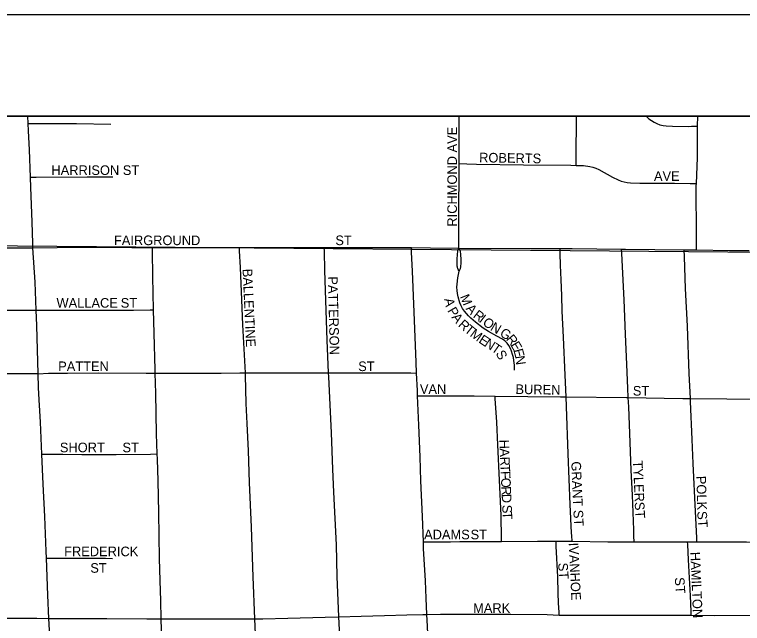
# Model space of a CAD drawing. Extents: x -9.1 to 34, y -3.1 to 22.
# Drawn here: x 5.381 to 6.099, y 20.4 to 21 of the extents above; entities that cross this region are included whole.
import ezdxf

# ---------------------------------------------------------------- set-up
doc = ezdxf.new("R2010")
doc.units = 0
for name, color, linetype in [('GM_X_City_Street', 7, 'Continuous'), ('GM_X_City_Street_Text', 7, 'Continuous'), ('GM_X_Corporation', 7, 'Continuous'), ('GM_X_Section', 7, 'Continuous'), ('GM_X_State_Route', 7, 'Continuous'), ('SH_Data', 7, 'Continuous')]:
    doc.layers.add(name, color=color, linetype=linetype)

msp = doc.modelspace()

# ---------------------------------------------------------------- linework, layer by layer
at = {"layer": 'GM_X_City_Street'}
for points in [[(5.3947, 20.89271), (5.39437, 20.9)], [(5.81948, 20.85303), (5.81945, 20.86152), (5.81951, 20.8769), (5.81946, 20.89235), (5.81958, 20.9)], [(5.93485, 20.85131), (5.93494, 20.86038), (5.93506, 20.87279), (5.93534, 20.88519), (5.93543, 20.89762), (5.93544, 20.9)], [(6.00374, 20.9), (6.00434, 20.89936), (6.00666, 20.89728), (6.00915, 20.89541), (6.01182, 20.8938), (6.01464, 20.89248), (6.01758, 20.89145), (6.0206, 20.89069), (6.02368, 20.89026), (6.0299, 20.88991), (6.04547, 20.88979), (6.04858, 20.88986), (6.05473, 20.88999)], [(6.05473, 20.88999), (6.05481, 20.9)], [(5.3947, 20.89271), (5.39889, 20.89269), (5.41123, 20.89261), (5.44208, 20.89272), (5.47601, 20.89207)], [(5.39691, 20.83962), (5.39575, 20.86667), (5.39504, 20.88525), (5.3947, 20.89271)], [(6.05349, 20.83337), (6.05452, 20.85892), (6.05473, 20.88999)], [(5.81931, 20.76967), (5.81932, 20.77473), (5.81941, 20.80646), (5.81952, 20.84428), (5.81948, 20.85303)], [(5.81948, 20.85303), (5.82724, 20.85281), (5.83656, 20.85254), (5.88318, 20.85185), (5.92982, 20.85146), (5.93485, 20.85131)], [(5.93485, 20.85131), (5.94225, 20.85109), (5.94843, 20.85036), (5.95145, 20.84965), (5.95437, 20.8486), (5.9572, 20.84731), (5.97078, 20.83974), (5.97636, 20.837), (5.97927, 20.83591), (5.98226, 20.83509), (5.98531, 20.83457), (5.98841, 20.83424), (5.99773, 20.83376), (6.0164, 20.83375), (6.03192, 20.8337), (6.04745, 20.83346), (6.05349, 20.83337)], [(5.39691, 20.83962), (5.40229, 20.83964), (5.45279, 20.83987), (5.47175, 20.83996), (5.47807, 20.83994)], [(5.39918, 20.77018), (5.39908, 20.77442), (5.39841, 20.79563), (5.39735, 20.82944), (5.39691, 20.83962)], [(6.0535, 20.768), (6.0535, 20.7734), (6.0535, 20.79361), (6.05332, 20.81863), (6.0534, 20.83103), (6.05349, 20.83337)], [(5.31853, 20.77025), (5.34775, 20.76989), (5.39737, 20.77016), (5.39918, 20.77018)], [(5.39918, 20.77018), (5.44701, 20.77059), (5.49665, 20.77048), (5.51709, 20.77037)], [(5.40252, 20.7086), (5.40215, 20.71792), (5.40135, 20.73619), (5.39918, 20.77018)], [(5.51709, 20.77037), (5.53386, 20.77028), (5.58659, 20.77038), (5.60286, 20.77033)], [(5.51828, 20.70896), (5.51745, 20.74181), (5.51714, 20.76683), (5.51709, 20.77037)], [(5.60888, 20.64679), (5.60726, 20.67648), (5.60632, 20.69398), (5.60541, 20.71888), (5.60381, 20.75055), (5.60302, 20.76712), (5.60286, 20.77033)], [(5.60286, 20.77033), (5.62383, 20.77033), (5.68277, 20.77032), (5.68658, 20.77033)], [(5.68658, 20.77033), (5.72, 20.7704), (5.77247, 20.77022)], [(5.69076, 20.64686), (5.68947, 20.679), (5.68721, 20.7478), (5.68668, 20.76687), (5.68658, 20.77033)], [(5.77247, 20.77022), (5.79137, 20.77015), (5.81931, 20.76967)], [(5.77757, 20.64658), (5.77704, 20.65738), (5.77604, 20.68211), (5.77505, 20.70671), (5.77353, 20.74705), (5.77267, 20.76591), (5.77247, 20.77022)], [(5.81973, 20.74696), (5.81926, 20.74772), (5.81869, 20.74874), (5.8183, 20.74958), (5.81805, 20.7504), (5.81788, 20.75114), (5.81777, 20.75199), (5.81763, 20.75305), (5.81756, 20.75404), (5.81753, 20.75527), (5.81769, 20.75893), (5.81789, 20.76352), (5.81825, 20.7666), (5.81864, 20.76827), (5.81931, 20.76967)], [(5.81973, 20.74696), (5.82035, 20.74838), (5.82081, 20.74966), (5.82117, 20.75118), (5.8213, 20.75253), (5.82141, 20.75383), (5.82148, 20.75527), (5.82159, 20.7583), (5.82121, 20.76364), (5.82076, 20.76635), (5.82018, 20.76808), (5.81931, 20.76967)], [(5.81931, 20.76967), (5.89064, 20.76929), (5.91913, 20.76927)], [(5.92505, 20.623), (5.92412, 20.64455), (5.92236, 20.68182), (5.92123, 20.70755), (5.92078, 20.72298), (5.92018, 20.73839), (5.91958, 20.75288), (5.91926, 20.76462), (5.91913, 20.76927)], [(5.91913, 20.76927), (5.93097, 20.76927), (5.9797, 20.76876)], [(5.98622, 20.62244), (5.98589, 20.63181), (5.985, 20.65488), (5.98369, 20.68505), (5.98217, 20.71885), (5.97992, 20.76448), (5.9797, 20.76876)], [(5.9797, 20.76876), (5.98371, 20.76873), (6.04161, 20.7682)], [(6.04764, 20.62159), (6.04641, 20.64632), (6.04462, 20.69288), (6.04285, 20.73011), (6.04184, 20.76116), (6.04161, 20.7682)], [(6.04161, 20.7682), (6.04267, 20.76819), (6.0535, 20.768)], [(6.0535, 20.768), (6.08609, 20.76743), (6.09513, 20.76738), (6.10549, 20.7674)], [(5.87414, 20.64933), (5.87414, 20.65212), (5.87405, 20.65438), (5.87357, 20.65893), (5.87303, 20.66201), (5.87228, 20.66504), (5.87134, 20.66802), (5.87017, 20.67091), (5.86871, 20.67366), (5.86691, 20.6762), (5.86469, 20.67837), (5.86215, 20.68015), (5.85671, 20.68306), (5.84849, 20.68754), (5.84327, 20.69099), (5.83582, 20.69669), (5.8311, 20.70078), (5.82884, 20.70294), (5.82673, 20.70523), (5.82476, 20.70765), (5.82294, 20.7102), (5.82145, 20.71293), (5.82031, 20.71584), (5.81854, 20.72183), (5.81788, 20.72489), (5.81749, 20.72798), (5.8174, 20.73111), (5.81753, 20.73423), (5.8183, 20.74044), (5.81973, 20.74696)], [(5.32126, 20.70844), (5.33072, 20.70845), (5.38395, 20.70852), (5.40252, 20.7086)], [(5.40252, 20.7086), (5.43023, 20.7087), (5.45591, 20.70871), (5.48041, 20.70871), (5.49827, 20.70872), (5.51494, 20.70889), (5.51828, 20.70896)], [(5.40449, 20.64596), (5.4032, 20.69363), (5.40252, 20.7086)], [(5.51992, 20.64652), (5.5198, 20.64988), (5.51886, 20.68597), (5.51828, 20.70896)], [(5.40449, 20.64596), (5.41473, 20.64637), (5.42067, 20.6465), (5.42715, 20.64663), (5.43336, 20.64665), (5.46433, 20.64671), (5.51076, 20.6465), (5.51992, 20.64652)], [(5.51992, 20.64652), (5.55717, 20.6466), (5.56946, 20.64665), (5.58483, 20.6466), (5.60335, 20.64679), (5.60888, 20.64679)], [(5.52185, 20.5669), (5.52126, 20.58674), (5.52046, 20.62686), (5.51992, 20.64652)], [(5.60888, 20.64679), (5.63737, 20.64683), (5.68391, 20.64691), (5.69076, 20.64686)], [(5.61799, 20.40438), (5.61651, 20.44562), (5.61479, 20.49456), (5.61295, 20.53886), (5.61178, 20.56995), (5.61042, 20.5969), (5.60963, 20.61663), (5.60896, 20.64465), (5.60888, 20.64679)], [(5.69076, 20.64686), (5.72274, 20.64682), (5.74862, 20.6469), (5.76103, 20.64683), (5.77203, 20.64667), (5.77757, 20.64658)], [(5.70101, 20.40644), (5.69939, 20.44603), (5.69846, 20.47721), (5.69608, 20.52917), (5.69502, 20.55179), (5.69357, 20.58771), (5.69092, 20.64282), (5.69076, 20.64686)], [(5.77864, 20.62419), (5.77843, 20.62937), (5.77757, 20.64658)], [(5.77864, 20.62419), (5.7837, 20.62416), (5.80782, 20.62405), (5.83446, 20.62402), (5.85506, 20.62378)], [(5.78429, 20.4803), (5.78326, 20.50505), (5.78191, 20.54032), (5.781, 20.56412), (5.77981, 20.59529), (5.77864, 20.62419)], [(5.86141, 20.48064), (5.86137, 20.48354), (5.86103, 20.5062), (5.8576, 20.5758), (5.8568, 20.59832), (5.85522, 20.62143), (5.85506, 20.62378)], [(5.85506, 20.62378), (5.91941, 20.62305), (5.92505, 20.623)], [(5.93089, 20.48076), (5.93055, 20.48612), (5.93034, 20.48922), (5.92905, 20.51716), (5.92714, 20.56688), (5.92545, 20.6135), (5.92505, 20.623)], [(5.92505, 20.623), (5.98453, 20.62247), (5.98622, 20.62244)], [(5.99218, 20.48012), (5.99199, 20.48572), (5.99177, 20.49194), (5.99042, 20.52614), (5.98917, 20.55099), (5.98812, 20.57808), (5.98681, 20.6133), (5.98622, 20.62244)], [(5.98622, 20.62244), (6.02163, 20.62189), (6.04009, 20.62167), (6.04764, 20.62159)], [(6.05402, 20.48031), (6.05386, 20.484), (6.05271, 20.51025), (6.05041, 20.55738), (6.04932, 20.58118), (6.0478, 20.6184), (6.04764, 20.62159)], [(6.04764, 20.62159), (6.0834, 20.62115), (6.10948, 20.62098)], [(5.40808, 20.56667), (5.41656, 20.56663), (5.42891, 20.56656), (5.44744, 20.56625), (5.48132, 20.56643), (5.51516, 20.5668), (5.52185, 20.5669)], [(5.52574, 20.40439), (5.52525, 20.42218), (5.52474, 20.44217), (5.52418, 20.46388), (5.52373, 20.48623), (5.52327, 20.509), (5.52263, 20.54025), (5.522, 20.56161), (5.52185, 20.5669)], [(5.78429, 20.4803), (5.79231, 20.48032), (5.81098, 20.4803), (5.82025, 20.48049), (5.83269, 20.4806), (5.85043, 20.4806), (5.86141, 20.48064)], [(5.78779, 20.40874), (5.78705, 20.42455), (5.7863, 20.44164), (5.78457, 20.47361), (5.78429, 20.4803)], [(5.86141, 20.48064), (5.89692, 20.48078), (5.91517, 20.48079)], [(5.91517, 20.48079), (5.92893, 20.4808), (5.93089, 20.48076)], [(5.9182, 20.40803), (5.91808, 20.41056), (5.91758, 20.42018), (5.91709, 20.42958), (5.91676, 20.44563), (5.91539, 20.47599), (5.91517, 20.48079)], [(5.93089, 20.48076), (5.96628, 20.48013), (5.99218, 20.48012)], [(5.99218, 20.48012), (6.00981, 20.48011), (6.04488, 20.48027)], [(6.04488, 20.48027), (6.05402, 20.48031)], [(6.04845, 20.4078), (6.04832, 20.4114), (6.04774, 20.42704), (6.04572, 20.46262), (6.045, 20.47768), (6.04488, 20.48027)], [(6.05402, 20.48031), (6.05611, 20.48032), (6.07057, 20.48032), (6.10309, 20.48009), (6.11475, 20.48001)], [(5.41263, 20.46423), (5.41766, 20.46424), (5.4221, 20.46424), (5.43169, 20.46424), (5.44998, 20.46424), (5.47084, 20.46416), (5.47785, 20.46391)], [(5.70101, 20.40644), (5.72301, 20.40709), (5.74584, 20.40775), (5.76802, 20.40824), (5.78382, 20.40867), (5.78779, 20.40874)], [(5.78779, 20.40874), (5.80116, 20.40896), (5.82547, 20.40897), (5.84075, 20.40897), (5.87049, 20.40882), (5.90647, 20.40849), (5.9182, 20.40803)], [(5.7908, 20.33829), (5.79053, 20.34463), (5.78927, 20.37389), (5.78828, 20.39705), (5.78779, 20.40874)], [(5.9182, 20.40803), (5.92541, 20.40795), (5.95314, 20.40796), (5.97141, 20.40796), (5.99682, 20.40802), (6.04845, 20.4078)], [(6.04845, 20.4078), (6.07132, 20.40769), (6.11017, 20.40788), (6.16608, 20.40802), (6.17968, 20.40788)], [(5.33461, 20.40522), (5.3385, 20.40522), (5.35252, 20.40522), (5.36568, 20.405), (5.38586, 20.40508), (5.40301, 20.40493), (5.41499, 20.40452)], [(5.41499, 20.40452), (5.42096, 20.40453), (5.47199, 20.4046), (5.51164, 20.40443), (5.5184, 20.4044), (5.52574, 20.40439)], [(5.52574, 20.40439), (5.54898, 20.40427), (5.56171, 20.40427), (5.59009, 20.40428), (5.6077, 20.40429), (5.61799, 20.40438)], [(5.5279, 20.31583), (5.52764, 20.32641), (5.5269, 20.36416), (5.52639, 20.38256), (5.52574, 20.40439)], [(5.61799, 20.40438), (5.62597, 20.40445), (5.65076, 20.40495), (5.68754, 20.40605), (5.70101, 20.40644)], [(5.62149, 20.31972), (5.62087, 20.33986), (5.61929, 20.37419), (5.61799, 20.40438)], [(5.70439, 20.32282), (5.70337, 20.34816), (5.70151, 20.39341), (5.70101, 20.40644)]]:
    msp.add_lwpolyline(points, dxfattribs=at)
at = {"layer": 'GM_X_Corporation'}
msp.add_line((6.49433, 20.9), (5.04128, 20.9), dxfattribs=at)
at = {"layer": 'GM_X_Section'}
msp.add_line((6.24144, 20.9), (5.22924, 20.9), dxfattribs=at)
msp.add_lwpolyline([(5.22924, 20.9), (5.2279, 20.77322), (6.2403, 20.76479), (6.24144, 20.9)], dxfattribs=at)
msp.add_lwpolyline([(5.2279, 20.77322), (6.2403, 20.76479), (6.2379, 19.76083), (5.226, 19.77229)], close=True, dxfattribs=at)
at = {"layer": 'GM_X_State_Route'}
for points in [[(5.40449, 20.64596), (5.39923, 20.64588), (5.38476, 20.64593), (5.35698, 20.64569), (5.32366, 20.64482)], [(5.42203, 20.25076), (5.42091, 20.26895), (5.41942, 20.29693), (5.41873, 20.31105), (5.41849, 20.31629), (5.41746, 20.34028), (5.41624, 20.36841), (5.41546, 20.39316), (5.41499, 20.40452), (5.41404, 20.42753), (5.41263, 20.46423), (5.41238, 20.471), (5.41109, 20.50504), (5.40943, 20.5372), (5.40808, 20.56667), (5.40663, 20.59827), (5.40616, 20.60942), (5.40556, 20.62026), (5.40491, 20.63224), (5.40449, 20.64596)]]:
    msp.add_lwpolyline(points, dxfattribs=at)
at = {"layer": 'SH_Data'}
for p, q in [((2.5, 21), (9.5, 21)), ((2.6, 20.9), (9.4, 20.9))]:
    msp.add_line(p, q, dxfattribs=at)

# ---------------------------------------------------------------- texts
at = {"layer": 'GM_X_City_Street_Text'}
for s, height, rotation, p in [('RICHMOND AVE', 0.0094697, 90, (5.81739, 20.79092)), ('ROBERTS', 0.00947, 359.08974, (5.83922, 20.85437)), ('HARRISON ST', 0.0094697, 0.00001, (5.41751, 20.84187)), ('AVE', 0.00947, 0.00001, (6.01168, 20.83604)), ('FAIRGROUND', 0.00947, 0.00001, (5.47918, 20.77271)), ('ST', 0.00947, 0.00001, (5.69751, 20.77271)), ('BALLENTINE', 0.00947, 272.63077, (5.60596, 20.74926)), ('PATTERSON', 0.00947, 271.43401, (5.69012, 20.7418)), ('M', 0.00947, 291.89273, (5.82014, 20.722)), ('WALLACE', 0.00947, 0.00001, (5.42251, 20.71104)), ('ST', 0.00947, 0.00001, (5.48584, 20.71104)), ('A', 0.00947, 281.24136, (5.80483, 20.71957)), ('P', 0.00947, 300.35564, (5.80768, 20.70819)), ('A', 0.00947, 311.09763, (5.82567, 20.70977)), ('R', 0.00947, 322.26907, (5.83261, 20.70211)), ('A', 0.00947, 306.46616, (5.81165, 20.70151)), ('I', 0.00947, 322.12502, (5.83854, 20.69753)), ('R', 0.00947, 317.91014, (5.81799, 20.69328)), ('T', 0.00947, 321.08821, (5.82399, 20.68788)), ('O', 0.00947, 323.03975, (5.84196, 20.69487)), ('N', 0.00947, 329.53201, (5.8496, 20.68921)), ('M', 0.00947, 323.57401, (5.82954, 20.68342)), ('G', 0.00947, 328.3653, (5.85887, 20.68371)), ('E', 0.00947, 326.75275, (5.83805, 20.67716)), ('N', 0.00947, 327.09076, (5.84368, 20.67347)), ('R', 0.00947, 309.03144, (5.86533, 20.67989)), ('T', 0.00947, 324.99903, (5.8506, 20.66899)), ('E', 0.00947, 300.49049, (5.86984, 20.67437)), ('S', 0.00947, 298.40991, (5.8553, 20.66603)), ('E', 0.00947, 285.20242, (5.87297, 20.66924)), ('PATTEN', 0.00947, 0.00001, (5.42418, 20.64853)), ('ST', 0.00947, 0.00001, (5.72001, 20.64853)), ('N', 0.00947, 278.11465, (5.87465, 20.66311)), ('VAN', 0.00947, 0.00001, (5.78084, 20.62604)), ('BUREN', 0.00947, 358.99377, (5.87505, 20.62603)), ('ST', 0.00947, 0.00001, (5.99084, 20.62437)), ('H', 0.00947, 271.224, (5.85929, 20.58087)), ('SHORT', 0.00947, 0.00001, (5.42584, 20.56853)), ('ST', 0.00947, 0.00001, (5.48751, 20.56853)), ('A', 0.00947, 272.4391, (5.85948, 20.57232)), ('R', 0.00947, 272.55859, (5.85984, 20.56397)), ('GRANT ST', 0.00947, 272.52471, (5.93012, 20.55933)), ('TYLER', 0.00947, 272.54837, (5.99095, 20.56017)), ('T', 0.00947, 272.57847, (5.86017, 20.55647)), ('F', 0.00947, 272.57847, (5.86047, 20.54981)), ('POLK', 0.00947, 271.59014, (6.05346, 20.54514)), ('O', 0.00947, 272.58588, (5.86077, 20.54315)), ('R', 0.00947, 272.57501, (5.86114, 20.53483)), ('D', 0.00947, 272.55791, (5.86148, 20.52734)), ('S', 0.00947, 272.56908, (5.86197, 20.51651)), ('ST', 0.00947, 273.57465, (5.99262, 20.51936)), ('T', 0.00947, 272.57847, (5.86226, 20.50985)), ('ST', 0.00947, 273.82568, (6.05429, 20.51021)), ('ADAMS', 0.00947, 0.00001, (5.78501, 20.4827)), ('ST', 0.00947, 0.00001, (5.83084, 20.4827)), ('IVANHOE', 0.00947, 272.69638, (5.92763, 20.4792)), ('FREDERICK', 0.00947, 0.00001, (5.43001, 20.46604)), ('HAMILTON', 0.00947, 272.32425, (6.04762, 20.47015)), ('ST', 0.00947, 0.00001, (5.45584, 20.44974)), ('ST', 0.00947, 273.57465, (5.91719, 20.45934)), ('ST', 0.00947, 273.58739, (6.03219, 20.44502)), ('MARK', 0.00947, 0.00001, (5.83334, 20.4102))]:
    msp.add_text(s, height=height, rotation=rotation, dxfattribs=at).set_placement(p)

doc.saveas('drawing.dxf')
